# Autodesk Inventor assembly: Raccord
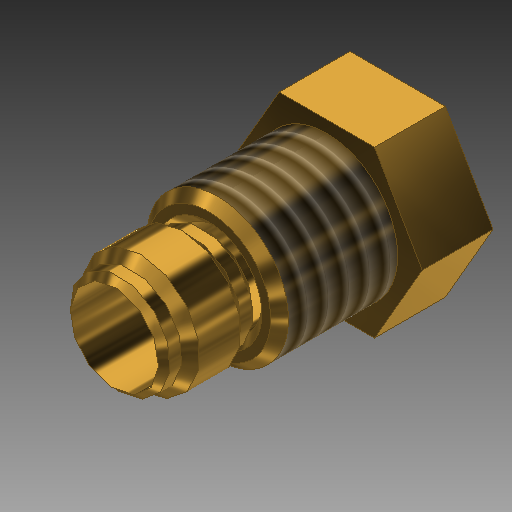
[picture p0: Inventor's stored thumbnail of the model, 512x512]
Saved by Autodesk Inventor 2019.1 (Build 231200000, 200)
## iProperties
Created: 2018-06
Part Number: Raccord
Material: Générique
Document SubType Name: Assembly
Designer: Fabian Perrée
Author: Fabian Perrée
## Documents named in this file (3)
- C:\Users\Fabian\Google Drive\04_CAO\01_Inventor\01_Fichiers_exercice_Inventor\01_Definitif\Capteur\Ens_raccord\Ens_raccord.iam
- C:\Users\Fabian\Google Drive\04_CAO\01_Inventor\01_Fichiers_exercice_Inventor\01_Definitif\Capteur\Ens_raccord\Composants\Bague.ipt
- C:\Users\Fabian\Google Drive\04_CAO\01_Inventor\01_Fichiers_exercice_Inventor\01_Definitif\Capteur\Ens_raccord\Composants\Vis_hexa.ipt
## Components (2 placed, 2 different names)
1. Bague:1
2. Vis_hexa:1
